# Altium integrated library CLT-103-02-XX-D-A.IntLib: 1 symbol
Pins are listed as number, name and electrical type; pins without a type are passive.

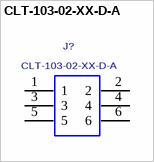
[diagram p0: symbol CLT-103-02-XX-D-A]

## CLT-103-02-XX-D-A
designator J?
LOW PROFILE SOCKET STRIP, 2mm PITCH, 6 PINS.; MANUFACTURER: SAMTEC
footprint CLT-103-02-XX-D-A
pins: 1, 2, 3, 4, 5, 6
